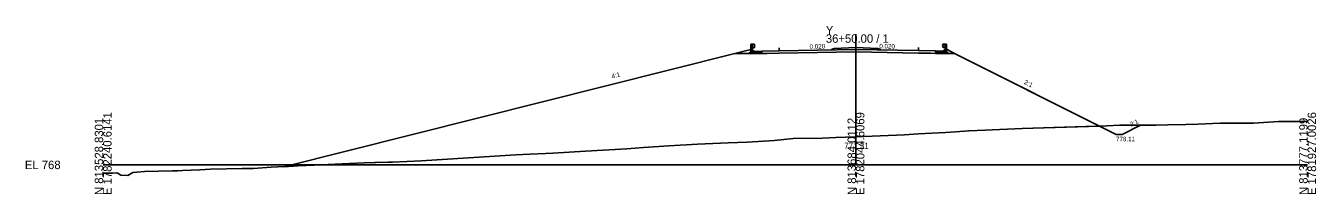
# Model space of a CAD drawing. Extents: x -12583 to 5303, y -44 to 25667.
# Drawn here: x 1874.3 to 2302.8, y 6990.3 to 7046.1 of the extents above; entities that cross this region are included whole.
import ezdxf

# ---------------------------------------------------------------- set-up
doc = ezdxf.new("R2010")
doc.units = 0
for name, color, linetype in [('Exist Cross Section Cell', 7, 'Continuous'), ('Exist XS Center Line Elevation Label', 7, 'Continuous'), ('Exist XS Ground Line', 7, 'Continuous'), ('Prop Conc 5in Monolithic Surface Mount Island', 7, 'Continuous'), ('Prop XS Ditch Standard Text', 7, 'Continuous'), ('Prop XS Dump Level', 7, 'Continuous'), ('Prop XS Earthwork Shape', 7, 'Continuous'), ('Prop XS EOT Tick Mark', 7, 'Continuous'), ('Prop XS Finish Grade', 7, 'Continuous'), ('Prop XS Finish Grade CurbGutter', 7, 'Continuous'), ('Prop XS Finish Grade Earthwork', 7, 'Continuous'), ('Prop XS Finish Grade Paved Shoulder', 7, 'Continuous'), ('Prop XS Finish Grade Pavement', 7, 'Continuous'), ('Prop XS Guardrail', 7, 'Continuous'), ('Prop XS Pvmt Edge Slope', 7, 'Continuous'), ('Prop XS SE Text', 7, 'Continuous'), ('Prop XS Side Slope Text', 7, 'Continuous'), ('Prop XS Subgrade CurbGutter', 7, 'Continuous'), ('Prop XS Subgrade Earthwork', 7, 'Continuous')]:
    doc.layers.add(name, color=color, linetype=linetype)

msp = doc.modelspace()

# ---------------------------------------------------------------- linework, layer by layer
at = {"layer": 'Exist Cross Section Cell'}
for p, q in [((2150, 7000), (2150, 7043.27)), ((1900, 7000), (2150, 7000)), ((2150, 7000), (2300, 7000))]:
    msp.add_line(p, q, dxfattribs=at)
at = {"layer": 'Exist XS Ground Line'}
for p, q in [((2179.73, 7010.73), (2183.02, 7010.97)), ((2183.02, 7010.97), (2187.5, 7011.32)), ((2187.5, 7011.32), (2192.87, 7011.5)), ((2192.87, 7011.5), (2205.17, 7012.05)), ((2205.17, 7012.05), (2233.28, 7012.95)), ((2233.28, 7012.95), (2237.58, 7013.2)), ((2237.58, 7013.2), (2246.06, 7013.15)), ((2246.06, 7013.15), (2249.74, 7013.14)), ((2249.74, 7013.14), (2253.58, 7013.26)), ((2253.58, 7013.26), (2259.57, 7013.4)), ((2259.57, 7013.4), (2263.55, 7013.54)), ((2263.55, 7013.54), (2271.02, 7013.81)), ((2271.02, 7013.81), (2280.45, 7013.83)), ((2280.45, 7013.83), (2281.98, 7013.85)), ((2281.98, 7013.85), (2290.33, 7014.42)), ((2290.33, 7014.42), (2297.2, 7014.4)), ((2297.2, 7014.4), (2299.64, 7014.38)), ((2299.64, 7014.38), (2300, 7014.39)), ((2087.88, 7006.27), (2097.38, 7006.84)), ((2097.38, 7006.84), (2107.61, 7007.34)), ((2107.61, 7007.34), (2113.87, 7007.54)), ((2113.87, 7007.54), (2122.93, 7008.07)), ((2122.93, 7008.07), (2129.11, 7008.7)), ((2129.11, 7008.7), (2138.9, 7008.91)), ((2138.9, 7008.91), (2143.27, 7009.05)), ((2143.27, 7009.05), (2150, 7009.31)), ((2150, 7009.31), (2166.11, 7009.95)), ((2166.11, 7009.95), (2170.72, 7010.24)), ((2170.72, 7010.24), (2179.73, 7010.73)), ((2005.56, 7001.32), (2037, 7003.3)), ((2037, 7003.3), (2041.69, 7003.51)), ((2041.69, 7003.51), (2046.92, 7003.72)), ((2046.92, 7003.72), (2049.33, 7003.9)), ((2049.33, 7003.9), (2054.7, 7004.22)), ((2054.7, 7004.22), (2060.18, 7004.51)), ((2060.18, 7004.51), (2073.95, 7005.34)), ((2073.95, 7005.34), (2079.45, 7005.77)), ((2079.45, 7005.77), (2087.88, 7006.27)), ((1913.73, 6997.8), (1922.97, 6997.99)), ((1922.97, 6997.99), (1924.79, 6998)), ((1924.79, 6998), (1926.38, 6998.13)), ((1926.38, 6998.13), (1932.13, 6998.39)), ((1932.13, 6998.39), (1935.62, 6998.54)), ((1935.62, 6998.54), (1946.11, 6998.77)), ((1946.11, 6998.77), (1947.79, 6998.75)), ((1947.79, 6998.75), (1949.9, 6998.85)), ((1949.9, 6998.85), (1955.82, 6999.2)), ((1955.82, 6999.2), (1964.81, 6999.67)), ((1964.81, 6999.67), (1970.11, 6999.96)), ((1970.11, 6999.96), (1979.35, 7000.39)), ((1979.35, 7000.39), (1986.64, 7000.64)), ((1986.64, 7000.64), (1990.2, 7000.74)), ((1990.2, 7000.74), (1990.51, 7000.75)), ((1990.51, 7000.75), (1994.65, 7000.87)), ((1994.65, 7000.87), (1996.11, 7000.9)), ((1996.11, 7000.9), (2005.56, 7001.32)), ((1900, 6997.26), (1900.63, 6997.26)), ((1900.63, 6997.26), (1902.49, 6997.29)), ((1902.49, 6997.29), (1903.1, 6997.3)), ((1903.1, 6997.3), (1904.64, 6997.34)), ((1904.64, 6997.34), (1904.97, 6997.11)), ((1904.97, 6997.11), (1905.86, 6996.56)), ((1905.86, 6996.56), (1908.24, 6996.47)), ((1908.24, 6996.47), (1909.81, 6997.46)), ((1909.81, 6997.46), (1911.18, 6997.61)), ((1911.18, 6997.61), (1913.73, 6997.8))]:
    msp.add_line(p, q, dxfattribs=at)
at = {"layer": 'Prop Conc 5in Monolithic Surface Mount Island'}
for p, q in [((2142, 7038.3), (2142.74, 7038.56)), ((2142, 7038.13), (2142, 7038.3)), ((2142.74, 7038.56), (2150, 7038.85)), ((2157.26, 7038.56), (2150, 7038.85)), ((2158, 7038.3), (2157.26, 7038.56)), ((2158, 7038.13), (2158, 7038.3))]:
    msp.add_line(p, q, dxfattribs=at)
at = {"layer": 'Prop XS Dump Level'}
for p, q in [((2124.45, 7037.78), (2150, 7038.29)), ((2150, 7038.29), (2170.75, 7037.87))]:
    msp.add_line(p, q, dxfattribs=at)
at = {"layer": 'Prop XS Earthwork Shape'}
for points in [[(1986.64, 7000.64), (1990.2, 7000.74), (1990.51, 7000.75), (1994.65, 7000.87), (1996.11, 7000.9), (2005.56, 7001.32), (2037, 7003.3), (2041.69, 7003.51), (2046.92, 7003.72), (2049.33, 7003.9), (2054.7, 7004.22), (2060.18, 7004.51), (2073.95, 7005.34), (2079.45, 7005.77), (2087.88, 7006.27), (2097.38, 7006.84), (2107.61, 7007.34), (2113.87, 7007.54), (2122.93, 7008.07), (2129.11, 7008.7), (2138.9, 7008.91), (2143.27, 7009.05), (2150, 7009.31), (2166.11, 7009.95), (2170.72, 7010.24), (2179.73, 7010.73), (2183.02, 7010.97), (2187.5, 7011.32), (2192.87, 7011.5), (2205.17, 7012.05), (2230.87, 7012.87), (2182.68, 7036.97), (2180.81, 7036.97), (2176.42, 7036.97), (2174.75, 7037), (2170.75, 7037.08), (2150, 7037.5), (2124.45, 7036.99), (2120.45, 7036.91), (2118.74, 7036.87), (2114.29, 7036.87), (2109.79, 7036.87), (1959.96, 6999.41), (1964.81, 6999.67), (1970.11, 6999.96), (1979.35, 7000.39)], [(2236.4, 7010.11), (2238.4, 7010.11), (2244.5, 7013.16), (2237.58, 7013.2), (2233.28, 7012.95), (2230.87, 7012.87)]]:
    msp.add_lwpolyline(points, close=True, dxfattribs=at)
at = {"layer": 'Prop XS EOT Tick Mark'}
for p, q in [((2124.45, 7037.78), (2124.45, 7038.78)), ((2170.75, 7037.87), (2170.75, 7038.87))]:
    msp.add_line(p, q, dxfattribs=at)
at = {"layer": 'Prop XS Finish Grade'}
for p, q in [((2115.11, 7038.2), (2109.79, 7036.87)), ((2115.7, 7037.91), (2115.11, 7038.2)), ((2179.44, 7038.01), (2180.02, 7038.3)), ((2182.68, 7036.97), (2180.02, 7038.3))]:
    msp.add_line(p, q, dxfattribs=at)
at = {"layer": 'Prop XS Finish Grade CurbGutter'}
for p, q in [((2116.4, 7037.57), (2115.7, 7037.91)), ((2118.74, 7037.66), (2116.4, 7037.57)), ((2176.42, 7037.76), (2178.75, 7037.67)), ((2178.75, 7037.67), (2179.44, 7038.01))]:
    msp.add_line(p, q, dxfattribs=at)
at = {"layer": 'Prop XS Finish Grade Earthwork'}
for p, q in [((2109.79, 7036.87), (1959.96, 6999.41)), ((2182.68, 7036.97), (2236.4, 7010.11)), ((2244.5, 7013.16), (2238.4, 7010.11)), ((2236.4, 7010.11), (2238.4, 7010.11))]:
    msp.add_line(p, q, dxfattribs=at)
at = {"layer": 'Prop XS Finish Grade Paved Shoulder'}
for p, q in [((2124.45, 7037.78), (2118.74, 7037.66)), ((2170.75, 7037.87), (2176.42, 7037.76))]:
    msp.add_line(p, q, dxfattribs=at)
at = {"layer": 'Prop XS Finish Grade Pavement'}
for p, q in [((2124.45, 7037.78), (2150, 7038.29)), ((2150, 7038.29), (2170.75, 7037.87))]:
    msp.add_line(p, q, dxfattribs=at)
at = {"layer": 'Prop XS Guardrail'}
for p, q in [((2115.07, 7037.47), (2115.07, 7039.97)), ((2115.07, 7039.97), (2115.57, 7039.97)), ((2115.57, 7039.97), (2115.57, 7037.47)), ((2115.57, 7039.97), (2116.07, 7039.97)), ((2116.07, 7038.83), (2115.57, 7038.83)), ((2116.07, 7039.97), (2116.37, 7039.77)), ((2116.37, 7039.65), (2116.07, 7039.45)), ((2116.07, 7039.45), (2116.07, 7039.35)), ((2116.07, 7039.35), (2116.37, 7039.15)), ((2116.37, 7039.03), (2116.07, 7038.83)), ((2116.37, 7039.77), (2116.4, 7039.71)), ((2116.4, 7039.71), (2116.37, 7039.65)), ((2116.37, 7039.15), (2116.4, 7039.09)), ((2116.4, 7039.09), (2116.37, 7039.03)), ((2178.78, 7039.86), (2178.75, 7039.8)), ((2178.75, 7039.8), (2178.78, 7039.74)), ((2178.78, 7039.25), (2178.75, 7039.19)), ((2178.75, 7039.19), (2178.78, 7039.13)), ((2179.07, 7040.06), (2178.78, 7039.86)), ((2178.78, 7039.74), (2179.07, 7039.54)), ((2179.07, 7039.45), (2178.78, 7039.25)), ((2178.78, 7039.13), (2179.07, 7038.93)), ((2179.57, 7040.06), (2179.07, 7040.06)), ((2179.07, 7039.54), (2179.07, 7039.45)), ((2179.07, 7038.93), (2179.57, 7038.93)), ((2180.07, 7040.06), (2179.57, 7040.06)), ((2179.57, 7040.06), (2179.57, 7037.56)), ((2180.07, 7037.56), (2180.07, 7040.06))]:
    msp.add_line(p, q, dxfattribs=at)
at = {"layer": 'Prop XS Pvmt Edge Slope'}
for p, q in [((2114.69, 7037.24), (2114.29, 7036.87)), ((2115.7, 7037.24), (2114.69, 7037.24)), ((2179.44, 7037.34), (2180.44, 7037.34)), ((2180.44, 7037.34), (2180.81, 7036.97))]:
    msp.add_line(p, q, dxfattribs=at)
at = {"layer": 'Prop XS Subgrade CurbGutter'}
for p, q in [((2115.7, 7037.24), (2115.7, 7037.91)), ((2118.74, 7037.24), (2115.7, 7037.24)), ((2118.74, 7037.66), (2118.74, 7037.24)), ((2176.42, 7037.76), (2176.42, 7037.34)), ((2176.42, 7037.34), (2179.44, 7037.34)), ((2179.44, 7037.34), (2179.44, 7038.01))]:
    msp.add_line(p, q, dxfattribs=at)
at = {"layer": 'Prop XS Subgrade Earthwork'}
for p, q in [((2114.29, 7036.87), (2109.79, 7036.87)), ((2118.74, 7036.87), (2114.29, 7036.87)), ((2120.45, 7036.91), (2118.74, 7036.87)), ((2124.45, 7036.99), (2120.45, 7036.91)), ((2150, 7037.5), (2124.45, 7036.99)), ((2170.75, 7037.08), (2150, 7037.5)), ((2170.75, 7037.08), (2174.75, 7037)), ((2174.75, 7037), (2176.42, 7036.97)), ((2176.42, 7036.97), (2176.42, 7036.97)), ((2176.42, 7036.97), (2180.81, 7036.97)), ((2180.81, 7036.97), (2182.68, 7036.97))]:
    msp.add_line(p, q, dxfattribs=at)

# ---------------------------------------------------------------- texts
at = {"layer": 'Exist Cross Section Cell'}
for s, p in [('Y', (2140, 7043.27)), ('36+50.00 / 1', (2140, 7040.47)), ('EL 768', (1874, 6998.6))]:
    msp.add_text(s, height=2.8, dxfattribs=at).set_placement(p)
for s, p in [('N 813528.8301', (1900, 6990)), ('E 1782240.6141', (1902.8, 6990)), ('N 813684.0112', (2150, 6990)), ('E 1782044.6069', (2152.8, 6990)), ('N 813777.1199', (2300, 6990)), ('E 1781927.0026', (2302.8, 6990))]:
    msp.add_text(s, height=2.8, rotation=90, dxfattribs=at).set_placement(p)
at = {"layer": 'Exist XS Center Line Elevation Label'}
msp.add_text('777.31', height=2, dxfattribs=at).set_placement((2146.08, 7005.31))
at = {"layer": 'Prop XS Ditch Standard Text'}
msp.add_text('778.11', height=1.5, dxfattribs=at).set_placement((2236.36, 7007.84))
at = {"layer": 'Prop XS Dump Level'}
msp.add_text('Case2', height=0.04, dxfattribs=at).set_placement((2176.42, 7037.72))
at = {"layer": 'Prop XS SE Text'}
for rotation, p in [(1.1458, (2134.6, 7038.48)), (358.8542, (2157.75, 7038.63))]:
    msp.add_text('0.020', height=1.5, rotation=rotation, dxfattribs=at).set_placement(p)
at = {"layer": 'Prop XS Side Slope Text'}
for s, rotation, p in [('4:1', 16.7601, (2069.08, 7028.55)), ('2:1', 333.4349, (2205.71, 7026.93)), ('2:1', 26.5651, (2241.4, 7012.63))]:
    msp.add_text(s, height=1.5, rotation=rotation, dxfattribs=at).set_placement(p)

doc.saveas('drawing.dxf')
